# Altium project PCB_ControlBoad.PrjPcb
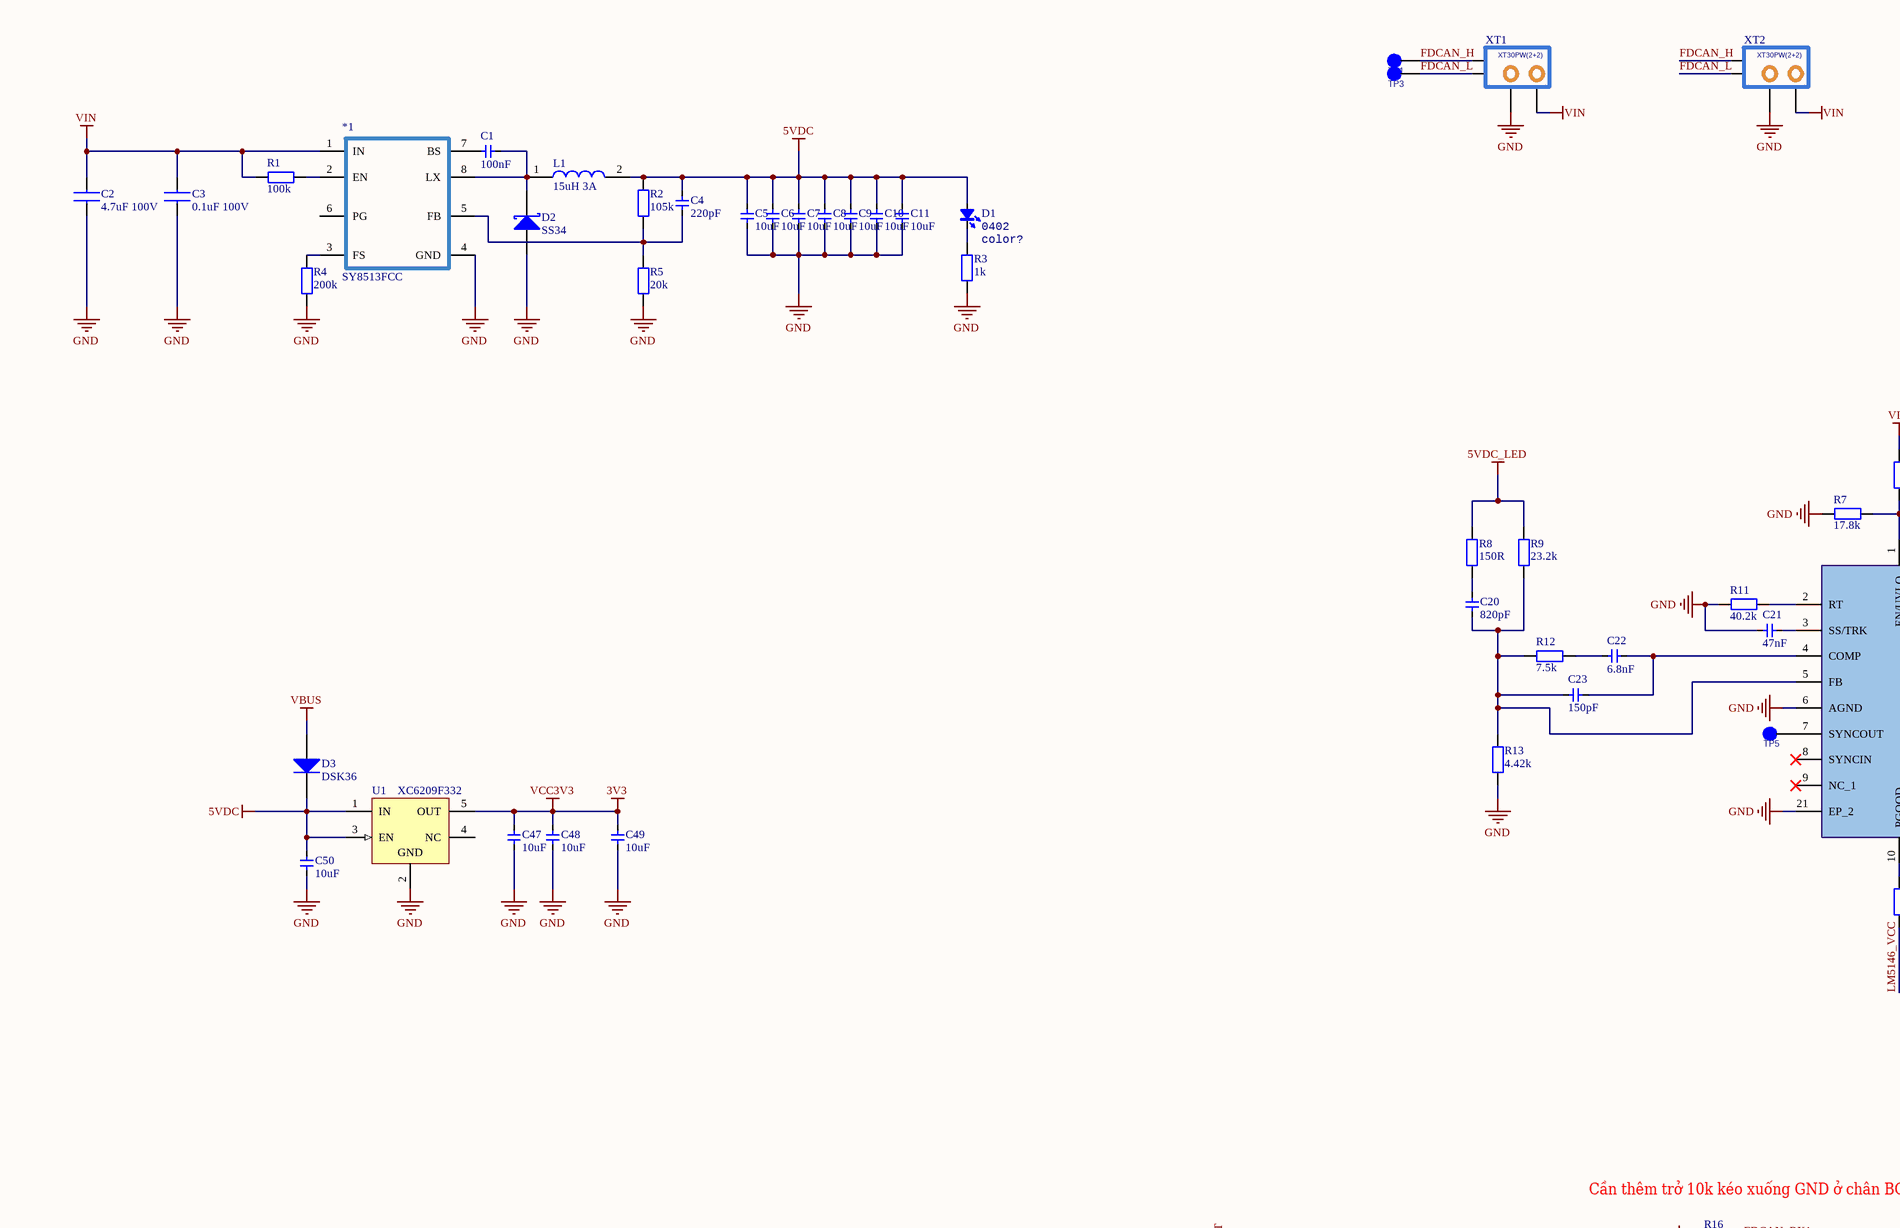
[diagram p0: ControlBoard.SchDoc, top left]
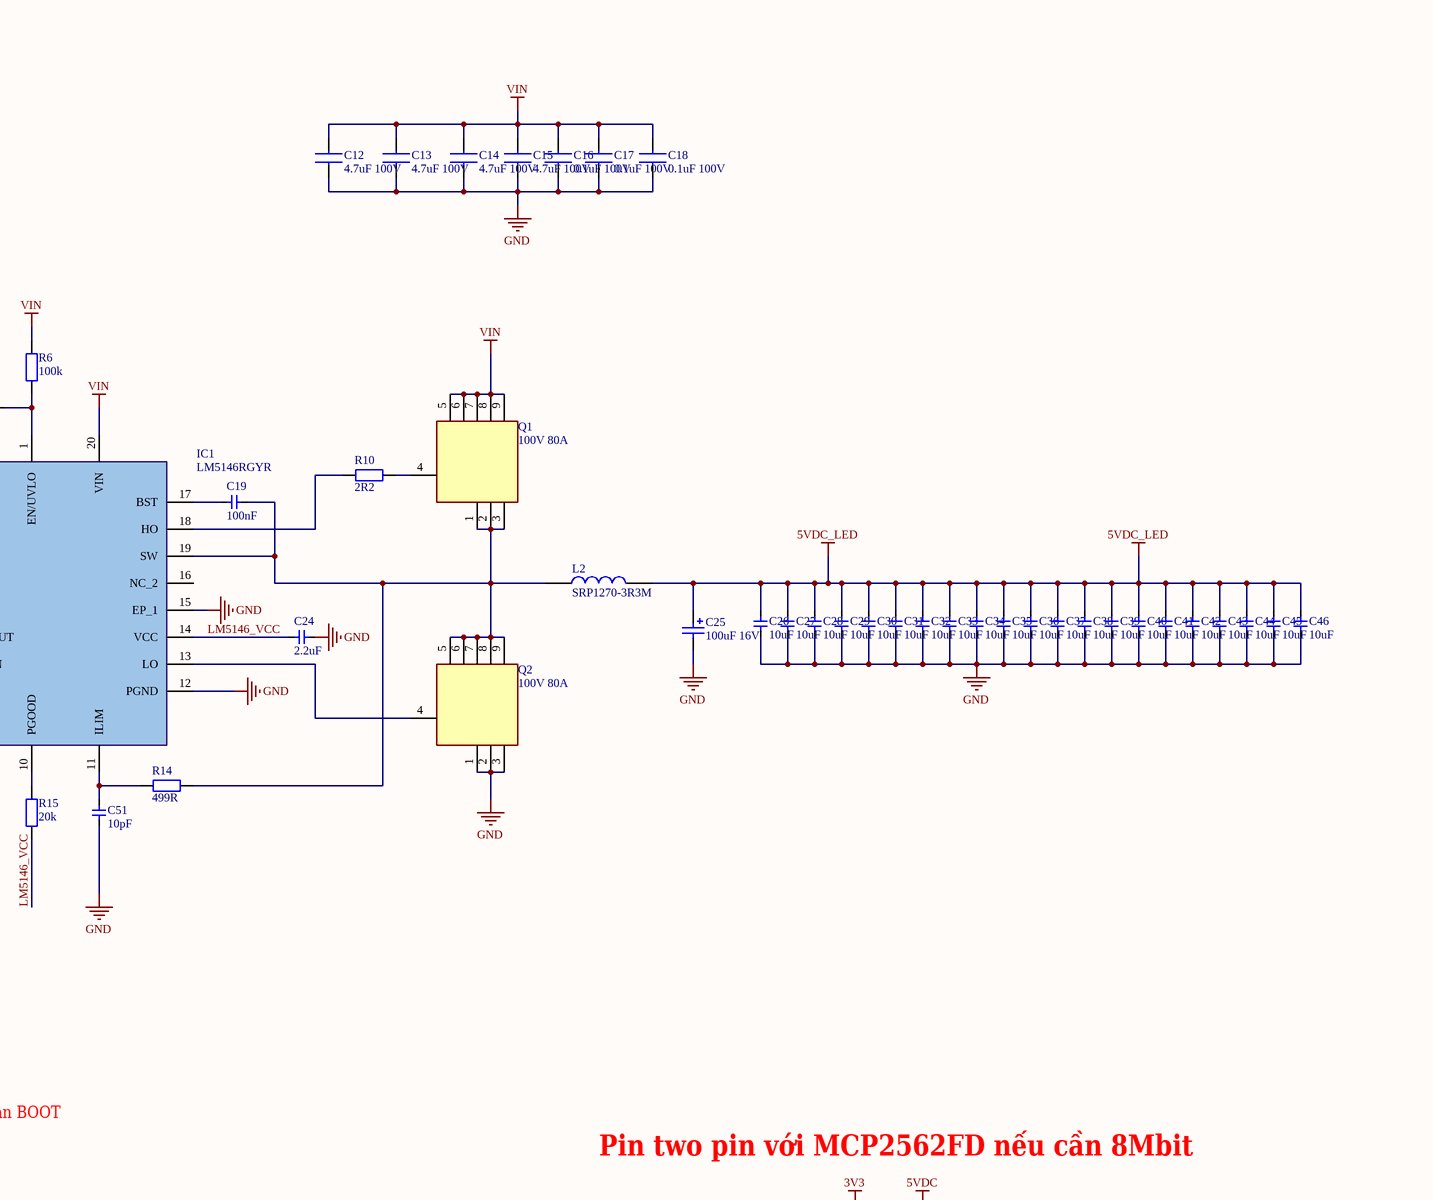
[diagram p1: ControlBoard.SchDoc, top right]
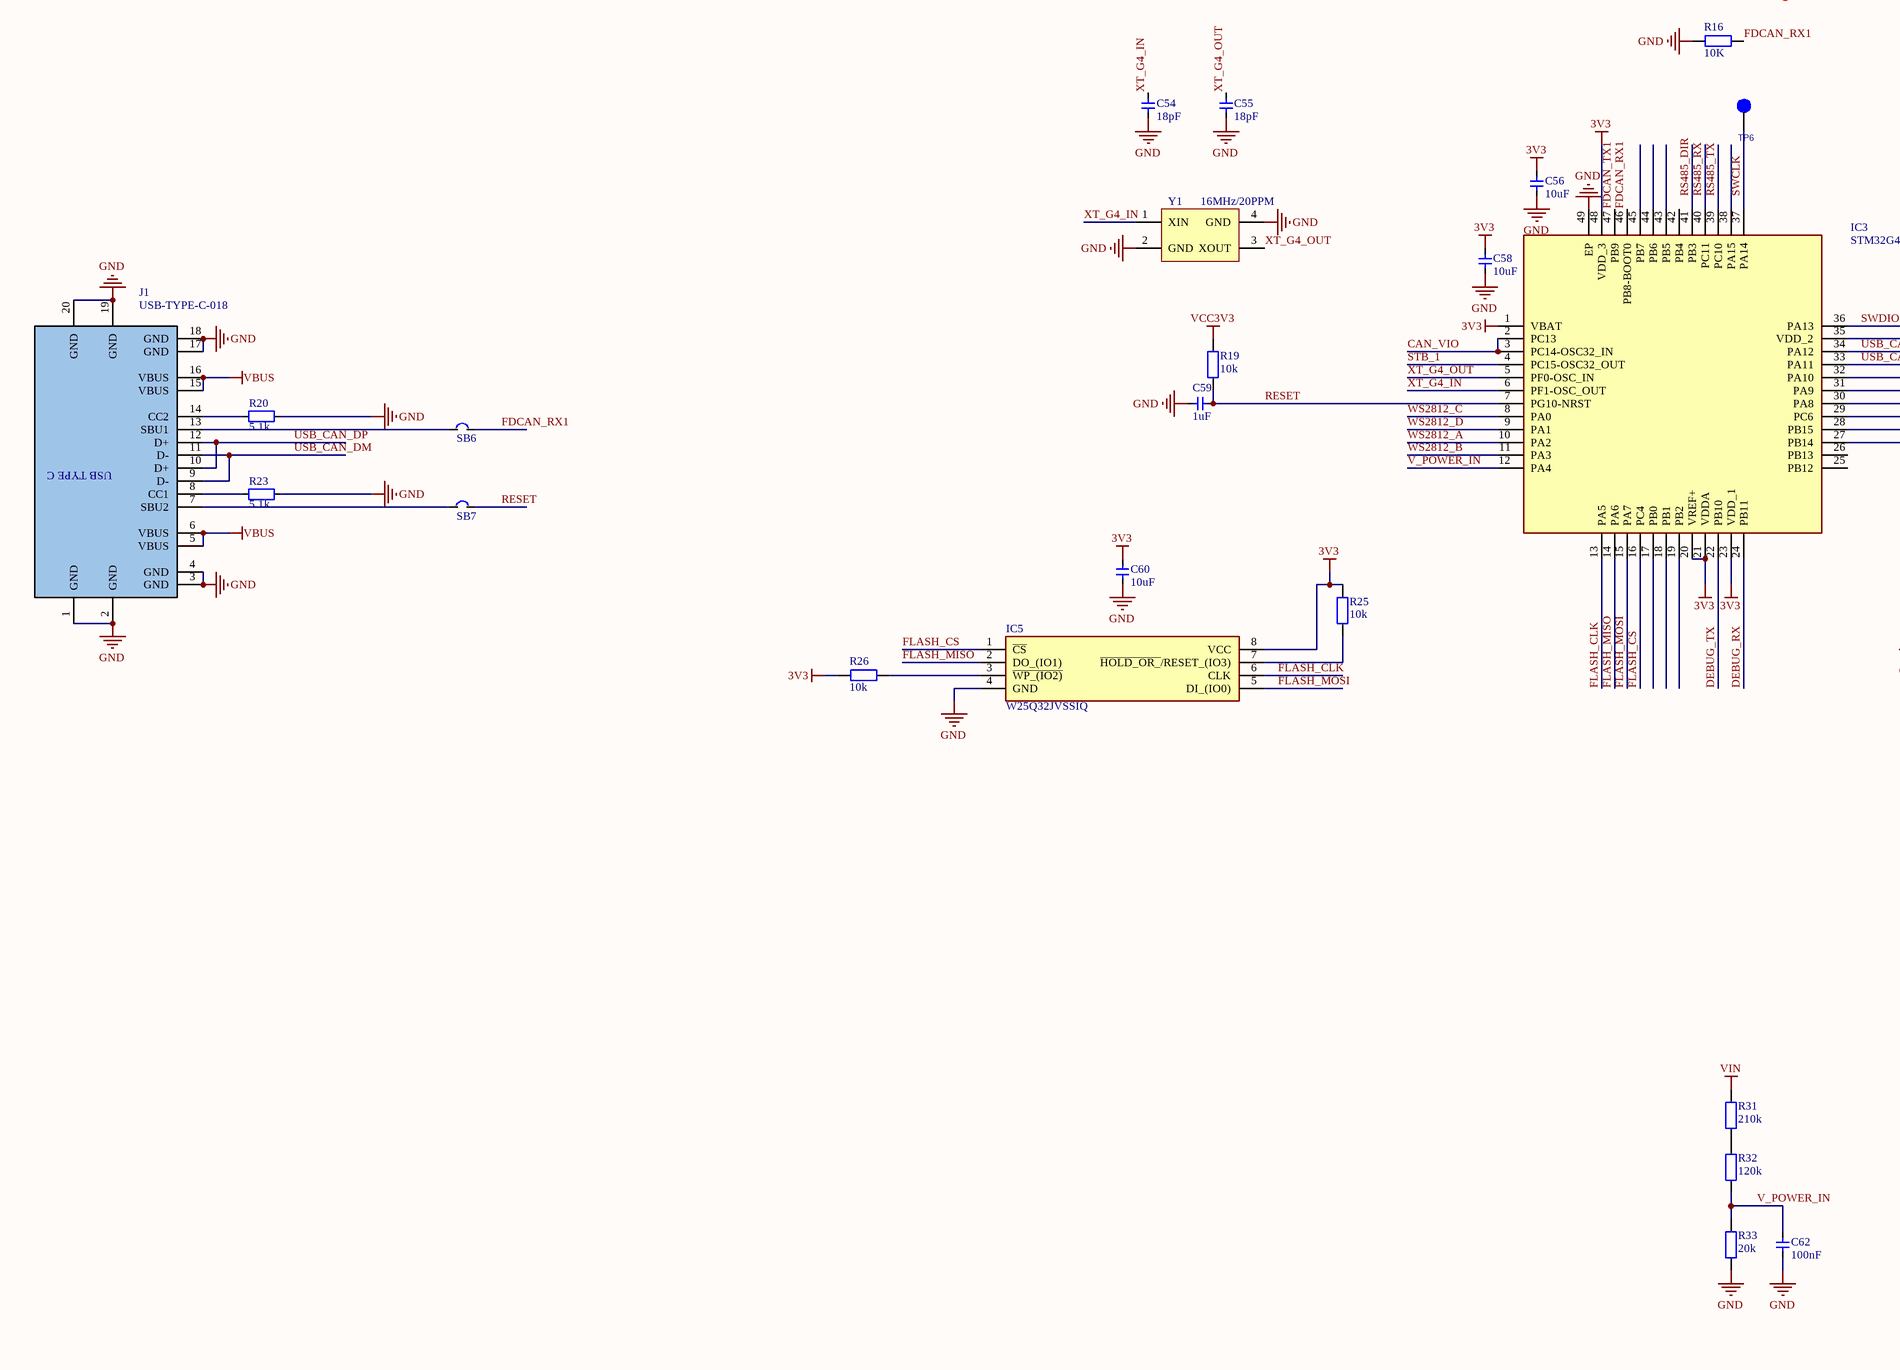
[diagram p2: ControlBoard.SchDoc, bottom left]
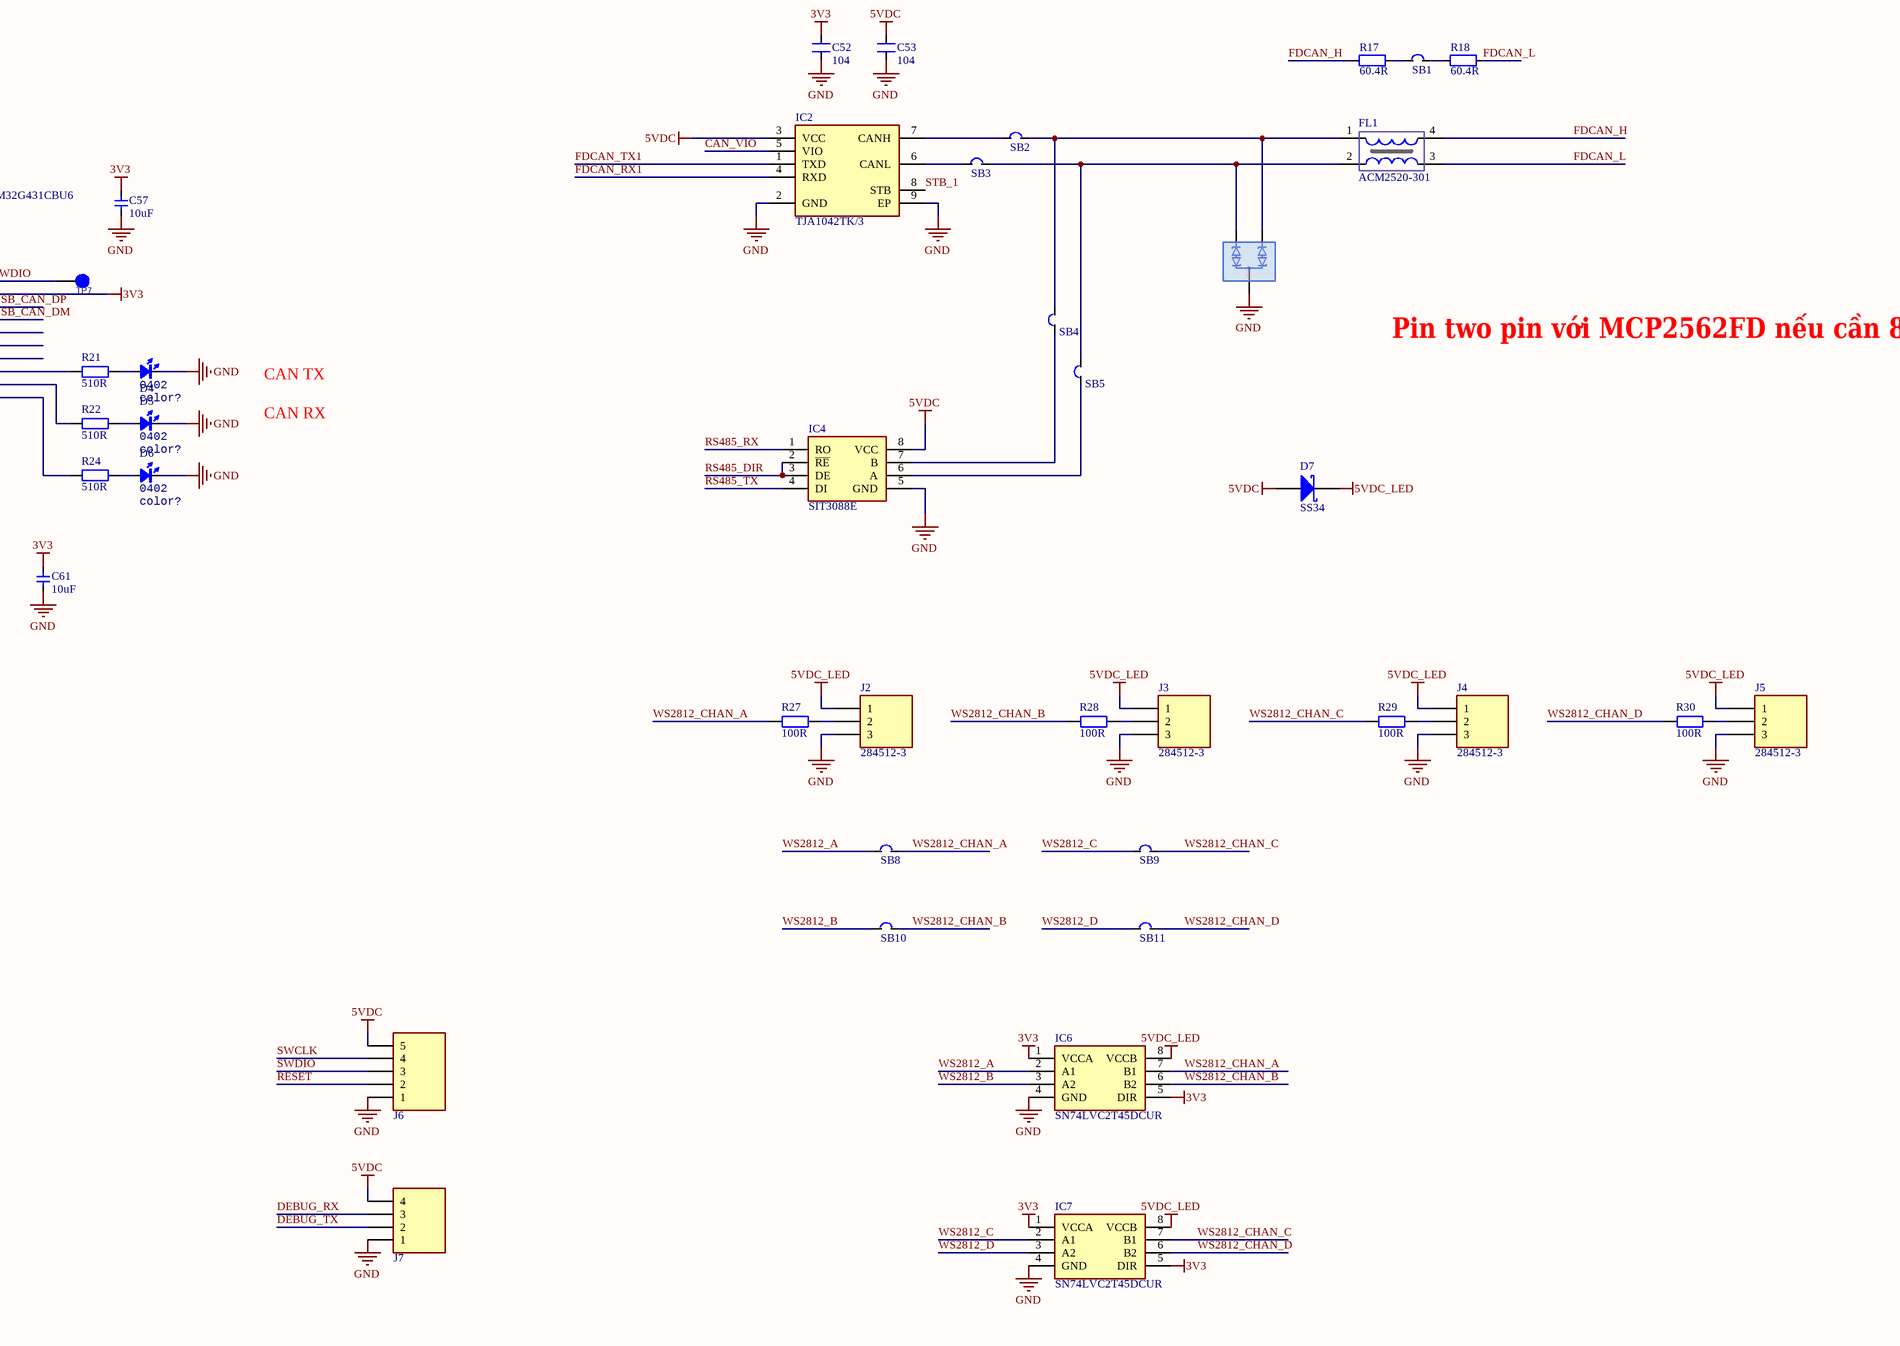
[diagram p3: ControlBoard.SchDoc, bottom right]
1 sheet, 143 parts. Net scope: global (net labels, ports and power ports of the same name join across sheets).
Board file: ControlBoard.PcbDoc

## Sheet ControlBoard.SchDoc
size A1; SheetNumber: 1; SheetTotal: 1

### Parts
*1  SY8513FCC  [SOIC127P600X170-9N]
C1  100nF  [CAP_0402]
C2  4.7uF 100V  [CAPC3225X200N]
C3  0.1uF 100V  [CAPC3225X200N]
C4  220pF  [CAP_0402]
C5  10uF  [CAP_0402]
C6  10uF  [CAP_0402]
C7  10uF  [CAP_0402]
C8  10uF  [CAP_0402]
C9  10uF  [CAP_0402]
C10  10uF  [CAP_0402]
C11  10uF  [CAP_0402]
C12  4.7uF 100V  [CAPC3225X200N]
C13  4.7uF 100V  [CAPC3225X200N]
C14  4.7uF 100V  [CAPC3225X200N]
C15  4.7uF 100V  [CAPC3225X200N]
C16  0.1uF 100V  [CAPC3225X200N]
C17  0.1uF 100V  [CAPC3225X200N]
C18  0.1uF 100V  [CAPC3225X200N]
C19  100nF  [CAP_0402]
C20  820pF  [CAP_0402]
C21  47nF  [CAP_0402]
C22  6.8nF  [CAP_0402]
C23  150pF  [CAP_0402]
C24  2.2uF  [CAP_0402]
C25  100uF 16V  [WCAP-AS5H_6.3x7.7]
C26  10uF  [CAP_0402]
C27  10uF  [CAP_0402]
C28  10uF  [CAP_0402]
C29  10uF  [CAP_0402]
C30  10uF  [CAP_0402]
C31  10uF  [CAP_0402]
C32  10uF  [CAP_0402]
C33  10uF  [CAP_0402]
C34  10uF  [CAP_0402]
C35  10uF  [CAP_0402]
C36  10uF  [CAP_0402]
C37  10uF  [CAP_0402]
C38  10uF  [CAP_0402]
C39  10uF  [CAP_0402]
C40  10uF  [CAP_0402]
C41  10uF  [CAP_0402]
C42  10uF  [CAP_0402]
C43  10uF  [CAP_0402]
C44  10uF  [CAP_0402]
C45  10uF  [CAP_0402]
C46  10uF  [CAP_0402]
C47  10uF  [CAP_0402_L]
C48  10uF  [CAP_0402_L]
C49  10uF  [CAP_0402_L]
C50  10uF  [CAP_0402_L]
C51  10pF  [CAP_0402]
C52  104  [CAP_0402]
C53  104  [CAP_0402]
C54  18pF  [CAP_0402]
C55  18pF  [CAP_0402]
C56  10uF  [CAP_0402]
C57  10uF  [CAP_0402]
C58  10uF  [CAP_0402]
C59  1uF  [CAP_0402]
C60  10uF  [CAP_0402]
C61  10uF  [CAP_0402]
C62  100nF  [CAP_0402]
CR1  PESD1CAN,215  [SOT23_PESD1_NEX]  (value not drawn)
D1  Type: 0402  [LED_0402_GREEN]  (hidden comment: color?)
D2  SS34  [DIODE_DO214AC_SMA]
D3  DSK36  [SOD123]
D4  Type: 0402  [LED_0402_BLUE]  (hidden comment: color?)
D5  Type: 0402  [LED_0402_RED]  (hidden comment: color?)
D6  Type: 0402  [LED_0402_GREEN]  (hidden comment: color?)
D7  SS34  [DIODE_DO214AC_SMA]
FL1  ACM2520-301  [ACM25203012P]
IC1  LM5146RGYR  [LM5146RGYR]
IC2  TJA1042TK/3  [SON65P300X300X100-9N]
IC3  STM32G431CBU6  [QFN50P700X700X65-49N-D]
IC4  SIT3088E  [SON65P300X300X100-9N]
IC5  W25Q32JVSSIQ  [SOIC127P790X216-8N]
IC6  SN74LVC2T45DCUR  [SOP50P310X90-8N]
IC7  SN74LVC2T45DCUR  [SOP50P310X90-8N]
J1  USB-TYPE-C-018  [USB4110GFA]
J2  284512-3  [SHDRRA3W80P0X350_1X3_1250X920X745P]
J3  284512-3  [SHDRRA3W80P0X350_1X3_1250X920X745P]
J4  284512-3  [SHDRRA3W80P0X350_1X3_1250X920X745P]
J5  284512-3  [SHDRRA3W80P0X350_1X3_1250X920X745P]
J6  SM05B-GHS-TB_LF__SN_  [SM05B-GHS-TB]  (value not drawn)
J7  SM04B-GHS-TB_LF__SN_  [SM04B-GHS-TB]  (value not drawn)
L1  15uH 3A  [INDPM5452X300N]
L2  SRP1270-3R3M  [INDPM137137X700N]
Q1  100V 80A  [BSC070N10NS5ATMA1]
Q2  100V 80A  [BSC070N10NS5ATMA1]
R1  100k  [RES_0402]
R2  105k  [RES_0402]
R3  1k  [RES_0402]
R4  200k  [RES_0402]
R5  20k  [RES_0402]
R6  100k  [RES_0402]
R7  17.8k  [RES_0402]
R8  150R  [RES_0402]
R9  23.2k  [RES_0402]
R10  2R2  [RES_0402]
R11  40.2k  [RES_0402]
R12  7.5k  [RES_0402]
R13  4.42k  [RES_0402]
R14  499R  [RES_0402]
R15  20k  [RES_0402]
R16  10K  [RES_0402]
R17  60.4R  [RES_0402]
R18  60.4R  [RES_0402]
R19  10k  [RES_0402]
R20  5.1k  [RES_0402]
R21  510R  [RES_0402]
R22  510R  [RES_0402]
R23  5.1k  [RES_0402]
R24  510R  [RES_0402]
R25  10k  [RES_0402]
R26  10k  [RES_0402]
R27  100R  [RESC1608X55N]
R28  100R  [RESC1608X55N]
R29  100R  [RESC1608X55N]
R30  100R  [RESC1608X55N]
R31  210k  [RES_0402]
R32  120k  [RES_0402]
R33  20k  [RES_0402]
SB1  Circuit Breaker  [SPST-2]  (value not drawn)
SB2  Circuit Breaker  [SPST-2]  (value not drawn)
SB3  Circuit Breaker  [SPST-2]  (value not drawn)
SB4  Circuit Breaker  [SPST-2]  (value not drawn)
SB5  Circuit Breaker  [SPST-2]  (value not drawn)
SB6  Circuit Breaker  [SPST-2]  (value not drawn)
SB7  Circuit Breaker  [SPST-2]  (value not drawn)
SB8  Circuit Breaker  [SPST-2]  (value not drawn)
SB9  Circuit Breaker  [SPST-2]  (value not drawn)
SB10  Circuit Breaker  [SPST-2]  (value not drawn)
SB11  Circuit Breaker  [SPST-2]  (value not drawn)
TP1  TP 1mm  [SMT Test Point]  (value not drawn)  (no BOM)
TP3  TP 1mm  [SMT Test Point]  (value not drawn)  (no BOM)
TP5  TP 1mm  [SMT Test Point]  (value not drawn)  (no BOM)
TP6  TP 1mm  [SMT Test Point]  (value not drawn)  (no BOM)
TP7  TP 1mm  [SMT Test Point]  (value not drawn)  (no BOM)
U1  XC6209F332  [SOT23-5]
XT1  XT30PW(2+2)  [XT30PW(2+2)]  (value not drawn)
XT2  XT30PW(2+2)  [XT30PW(2+2)]  (value not drawn)
Y1  16MHz/20PPM  [XT-2520]

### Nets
3V3: C47.1 C48.1 C49.1 C52.1 C56.2 C57.2 C58.2 C60.1 C61.2 IC3.1(VBAT) IC3.20(VREF+) IC3.21(VDDA) IC3.23(VDD_1) IC3.35(VDD_2) IC3.48(VDD_3) IC5.8(VCC) IC6.1(VCCA) IC6.5(DIR) IC7.1(VCCA) IC7.5(DIR) R19.1 R25.2 R26.2 U1.5(OUT)  [also labelled VCC3V3]
5VDC: C4.2 C5.2 C6.2 C7.2 C8.2 C9.2 C10.2 C11.2 C50.1 C53.1 D1.1(A) D3.2(K) D7.1(A) IC2.3(VCC) IC4.8(VCC) J6.5 J7.4 L1.2 R2.1 U1.1(IN) U1.3(EN)
5VDC_LED: C25.1(P) C26.2 C27.2 C28.2 C29.2 C30.2 C31.2 C32.2 C33.2 C34.2 C35.2 C36.2 C37.2 C38.2 C39.2 C40.2 C41.2 C42.2 C43.2 C44.2 C45.2 C46.2 D7.2(K) IC6.8(VCCB) IC7.8(VCCB) J2.1 J3.1 J4.1 J5.1 L2.2 R8.1 R9.1
GND: *1.4(GND) C2.1 C3.1 C5.1 C6.1 C7.1 C8.1 C9.1 C10.1 C11.1 C12.1 C13.1 C14.1 C15.1 C16.1 C17.1 C18.1 C21.1 C24.2 C25.2(N) C26.1 C27.1 C28.1 C29.1 C30.1 C31.1 C32.1 C33.1 C34.1 C35.1 C36.1 C37.1 C38.1 C39.1 C40.1 C41.1 C42.1 C43.1 C44.1 C45.1 C46.1 C47.2 C48.2 C49.2 C50.2 C51.2 C52.2 C53.2 C54.1 C55.1 C56.1 C57.1 C58.1 C59.2 C60.2 C61.1 C62.2 CR1.3 D2.1(A) D4.2(K) D5.2(K) D6.2(K) IC1.6(AGND) IC1.12(PGND) IC1.15(EP_1) IC1.21(EP_2) IC2.2(GND) IC2.9(EP) IC3.49(EP) IC4.5(GND) IC5.4(GND) IC6.4(GND) IC7.4(GND) J1.1(GND) J1.2(GND) J1.3(GND) J1.4(GND) J1.17(GND) J1.18(GND) J1.19(GND) J1.20(GND) J2.3 J3.3 J4.3 J5.3 J6.1 J7.1 Q2.1(S_1) Q2.2(S_2) Q2.3(S_3) R3.1 R4.2 R5.2 R7.2 R11.2 R13.2 R16.1 R20.1 R23.1 R33.2 U1.2(GND) XT1.2 XT2.2 Y1.2(GND) Y1.4(GND)
VBUS: D3.1(A) J1.5(VBUS) J1.6(VBUS) J1.15(VBUS) J1.16(VBUS)
VIN: *1.1(IN) C2.2 C3.2 C12.2 C13.2 C14.2 C15.2 C16.2 C17.2 C18.2 IC1.20(VIN) Q1.5(D_1) Q1.6(D_2) Q1.7(D_3) Q1.8(D_4) Q1.9(D_5) R1.1 R6.2 R31.1 XT1.1 XT2.1
CAN_VIO: IC2.5(VIO) IC3.2(PC13) IC3.3(PC14-OSC32_IN)
DEBUG_RX: IC3.24(PB11) J7.3
DEBUG_TX: IC3.22(PB10) J7.2
FDCAN_H: FL1.4 R17.1 TP1.1(TP) XT1.4 XT2.4
FDCAN_L: FL1.3 R18.2 TP3.1(TP) XT1.3 XT2.3
FDCAN_RX1: IC2.4(RXD) IC3.46(PB8-BOOT0) R16.2 SB6.2
FDCAN_TX1: IC2.1(TXD) IC3.47(PB9)
FLASH_CLK: IC3.13(PA5) IC5.6(CLK)
FLASH_CS: IC3.16(PC4) IC5.1(~{CS})
FLASH_MISO: IC3.14(PA6) IC5.2(DO_(IO1))
FLASH_MOSI: IC3.15(PA7) IC5.5(DI_(IO0))
LM5146_VCC: C24.1 IC1.14(VCC) R15.1
RESET: C59.1 IC3.7(PG10-NRST) J6.2 R19.2 SB7.2
RS485_DIR: IC3.41(PB3) IC4.2(~{RE}) IC4.3(DE)
RS485_RX: IC3.40(PC11) IC4.1(RO)
RS485_TX: IC3.39(PC10) IC4.4(DI)
STB_1: IC2.8(STB) IC3.4(PC15-OSC32_OUT)
SWCLK: IC3.37(PA14) J6.4 TP6.1(TP)
SWDIO: IC3.36(PA13) J6.3 TP7.1(TP)
USB_CAN_DM: IC3.33(PA11) J1.9(D-) J1.11(D-)
USB_CAN_DP: IC3.34(PA12) J1.10(D+) J1.12(D+)
V_POWER_IN: C62.1 IC3.12(PA4) R32.2 R33.1
WS2812_A: IC3.10(PA2) IC6.2(A1) SB8.1
WS2812_B: IC3.11(PA3) IC6.3(A2) SB10.1
WS2812_C: IC3.8(PA0) IC7.2(A1) SB9.1
WS2812_CHAN_A: IC6.7(B1) R27.1 SB8.2
WS2812_CHAN_B: IC6.6(B2) R28.1 SB10.2
WS2812_CHAN_C: IC7.7(B1) R29.1 SB9.2
WS2812_CHAN_D: IC7.6(B2) R30.1 SB11.2
WS2812_D: IC3.9(PA1) IC7.3(A2) SB11.1
XT_G4_IN: C54.2 IC3.6(PF1-OSC_OUT) Y1.1(XIN)
XT_G4_OUT: C55.2 IC3.5(PF0-OSC_IN) Y1.3(XOUT)
Net*1_2: *1.2(EN) R1.2
Net*1_3: *1.3(FS) R4.1
Net*1_5: *1.5(FB) C4.1 R2.2 R5.1
Net*1_7: *1.7(BS) C1.2
Net*1_8: *1.8(LX) C1.1 D2.2(K) L1.1
NetC19_1: C19.1 IC1.17(BST)
NetC19_2: C19.2 IC1.19(SW) L2.1 Q1.1(S_1) Q1.2(S_2) Q1.3(S_3) Q2.5(D_1) Q2.6(D_2) Q2.7(D_3) Q2.8(D_4) Q2.9(D_5) R14.2
NetC20_1: C20.1 C23.1 IC1.5(FB) R9.2 R12.2 R13.1
NetC20_2: C20.2 R8.2
NetC21_2: C21.2 IC1.3(SS/TRK)
NetC22_1: C22.1 R12.1
NetC22_2: C22.2 C23.2 IC1.4(COMP)
NetC51_1: C51.1 IC1.11(ILIM) R14.1
NetCR1_1: CR1.1 FL1.1 SB2.2 SB4.2
NetCR1_2: CR1.2 FL1.2 SB3.2 SB5.2
NetD1_2: D1.2(K) R3.2
NetD4_1: D4.1(A) R21.2
NetD5_1: D5.1(A) R22.2
NetD6_1: D6.1(A) R24.2
NetIC1_1: IC1.1(EN/UVLO) R6.1 R7.1
NetIC1_2: IC1.2(RT) R11.1
NetIC1_7: IC1.7(SYNCOUT) TP5.1(TP)
NetIC1_10: IC1.10(PGOOD) R15.2
NetIC1_13: IC1.13(LO) Q2.4(G)
NetIC1_18: IC1.18(HO) R10.2
NetIC2_6: IC2.6(CANL) SB3.1
NetIC2_7: IC2.7(CANH) SB2.1
NetIC3_27: IC3.27(PB14) R24.1
NetIC3_28: IC3.28(PB15) R22.1
NetIC3_29: IC3.29(PC6) R21.1
NetIC4_6: IC4.6(A) SB5.1
NetIC4_7: IC4.7(B) SB4.1
NetIC5_3: IC5.3(~{WP_(IO2)}) R26.1
NetIC5_7: IC5.7(~{HOLD_OR_}/RESET_(IO3)) R25.1
NetJ1_7: J1.7(SBU2) SB7.1
NetJ1_8: J1.8(CC1) R23.2
NetJ1_13: J1.13(SBU1) SB6.1
NetJ1_14: J1.14(CC2) R20.2
NetJ2_2: J2.2 R27.2
NetJ3_2: J3.2 R28.2
NetJ4_2: J4.2 R29.2
NetJ5_2: J5.2 R30.2
NetQ1_4: Q1.4(G) R10.1
NetR17_2: R17.2 SB1.1
NetR18_1: R18.1 SB1.2
NetR31_2: R31.2 R32.1

Not connected (* = marked no-connect by the designer): *1 6(PG); IC1 8(SYNCIN)* 9(NC_1)* 16(NC_2); IC3 17(PB0) 18(PB1) 19(PB2) 25(PB12) 26(PB13) 30(PA8) 31(PA9) 32(PA10) 38(PA15) 42(PB4) 43(PB5) 44(PB6) 45(PB7); U1 4(NC)

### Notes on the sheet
- (near R16) Cần thêm trở 10k kéo xuống GND ở chân BOOT
- Pin two pin với MCP2562FD nếu cần 8Mbit
- CAN TX
- CAN RX

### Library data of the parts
C1 C4-C11 C19-C24 C26-C51 C54-C62 = C_0402: Capacitor; Value: 0.1u
C2 C3 C12-C18 = C_1210: X7R 100V 1uF ±10% 1210 Multilayer Ceramic Capacitors MLCC - SMD/SMT ROHS; Manufacturer_Name: TDK; Manufacturer_Part_Number: C3225X7S3D102M200AA
C25 = CAP/100uF/16V/865230345005: WCAP-AS5H Aluminum Electrolytic Capacitors, 100uF
C52 C53 = CM: Cap SMD; Value: 103
CR1 = PESD1CAN,215: No Description Available; Mfr_Name: Nexperia
D1 = LED_0402: LED RES
D2 D7 = SS34: DIODE SCHOTTKY 40V 3A SMA; Solder: SMT
D3 = 1N4007 SOD123: DSK36 60V 3A
D4-D6 = LED_0402: LED
FL1 = ACM2520-301-2PL-TL01_1: Common Mode Filters; Manufacturer_Name: TDK; Manufacturer_Part_Number: ACM9070-701-2PL-TL01
IC1 = LM5146RGYR: Integrated Circuit; Manufacturer_Name: Texas Instruments
IC2 = SIT1044QTK/3: https://item.taobao.com/item.htm?spm=a21n57.1.0.0.730f50e55xYJuK&id=715328337189&ns=1&abbucket=13#detail; Manufacturer_Name: NXP; Manufacturer_Part_Number: TJA1044VTKZ
IC3 = STM32G431CBU6: Integrated Circuit; Manufacturer_Name: STMicroelectronics
IC4 = SIT3088E: Integrated Circuit; Manufacturer_Name: Texas Instruments; Manufacturer_Part_Number: SN65HVD485EDGKR
IC5 = W25Q32JVSSIQ: Integrated Circuit; Manufacturer_Name: Winbond
IC6 IC7 = SN74LVC2T45DCUR: Integrated Circuit; Manufacturer_Name: Texas Instruments
J1 = USB4110-GF-A: USB-TYPE-C-018 C2927038 3A 1 Horizontal attachment 16P Female -25℃~+85℃ Type-C SMD USB Connectors ROHS; Manufacturer_Name: GCT (GLOBAL CONNECTOR TECHNOLOGY)
J2-J5 = 284512-3: 284512-3 3P 3.5mm; Manufacturer_Name: TE Connectivity
J6 = SM05B-GHS-TB_LF__SN_: 1.25mm Pitch 5 Way Shrouded Right Angle PCB Header; Manufacturer_Name: JST (JAPAN SOLDERLESS TERMINALS); Manufacturer_Part_Number: SM05B-GHS-TB(LF)(SN)
J7 = SM04B-GHS-TB_LF__SN_: 1.25mm Pitch 4 Way Shrouded Right Angle PCB Header; Manufacturer_Name: JST (JAPAN SOLDERLESS TERMINALS); Manufacturer_Part_Number: SM04B-GHS-TB(LF)(SN)
L1 = SLO0530H3R3MTT: SMMS0530-100M; Manufacturer_Name: Sunltech Tech
L2 = SRP1270-3R3M: SRP1270-3R3M 13.7*13.7mm; Manufacturer_Name: Bourns
Q1 Q2 = BSC070N10NS5: BSC070N10NS5 MOSFET (N-Channel); Manufacturer_Name: onsemi; Manufacturer_Part_Number: NTMFS5C628NLT3G
R1-R16 R19 R21 R22 R24-R26 R31-R33 = R: Resistor R1/4W
R17 R18 R20 R23 = R-0402: Resistor; Value: 22R
R27-R30 = R_0603: Resistor R1/4W
SB1-SB11 = CB: Solder: NO
TP1 TP3 TP5-TP7 = TP 1mm: PCB TEST POINT SMT 1mm
U1 = XC6209F332MR-G: IC REG LINEAR 3.3V 300MA SOT25; MFR: Torex Semiconductor Ltd; Solder: SMT
Y1 = XT-4Pin: XT-2520; MF: ECS International; MP: ECS-3225S30-240-EN-TR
